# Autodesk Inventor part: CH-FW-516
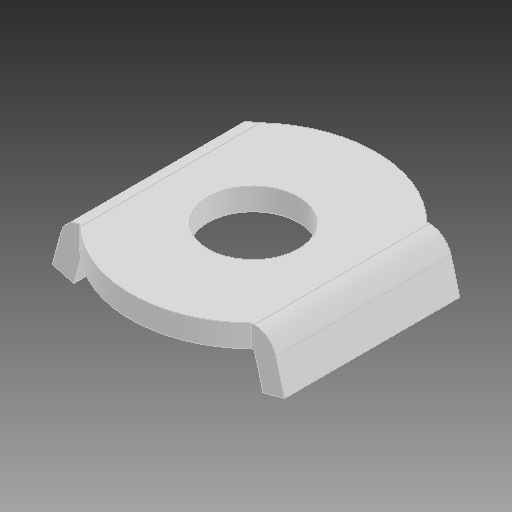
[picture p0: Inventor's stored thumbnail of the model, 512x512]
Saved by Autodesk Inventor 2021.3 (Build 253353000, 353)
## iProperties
Created: 2020-03
Part Number: CH-FW-516
Material: Ogólny
Document SubType Name: Modeling
Designer: Przemyslaw Krecisz
Density: 1 g/cm^3
Appearance: Domyślna
Author: Przemyslaw Krecisz
Revision Number: ÈÎºÎ
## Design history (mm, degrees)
feature "ÇÐ³ý-À­Éì3"
node "Bryła1"
